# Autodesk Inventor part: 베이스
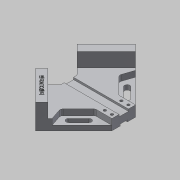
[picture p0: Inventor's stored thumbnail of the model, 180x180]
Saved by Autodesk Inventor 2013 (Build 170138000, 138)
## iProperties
Created: 2019-04
Part Number: 베이스
Material: 알루미늄 6061
Document SubType Name: Modeling
Designer: Administrator
Density: 2.71 g/cm^3
Mass: 603.672 g
Surface Area: 425.327 cm^2
Volume: 222.757 cm^3
Author: Administrator
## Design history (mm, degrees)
sketch "스케치1"
  geometry: L1 (84.853, 0)-(35.355, 49.497); L2 (0, 84.853)-(-35.355, 49.497); L3 (-84.853, 0)-(-20, -64.853); L4 (0, -84.853)-(20, -64.853); L5 (84.853, 0)-(-84.853, 0); L6 (0, 84.853)-(0, -84.853); L7 (-35.355, 49.497)-(-14.005, 28.147); L8 (-14.005, 28.147)-(14.005, 28.147); L9 (14.005, 28.147)-(35.355, 49.497); L10 (-20, -64.853)-(20, -64.853); L11 (20, -64.853)-(84.853, 0); L12 (-20, -64.853)-(0, -84.853); L13 (-35.355, 49.497)-(-84.853, 0); L14 (35.355, 49.497)-(0, 84.853); 4 further points
  constraints: 28 end point, 8 parallel, 5 midpoint, 4 perpendicular, 2 horizontal, 2 vertical alignment, 1 equal length
  dimensions: "d0" = 120 distance of L1.start L2.start; "d2" = 50 distance of L2.start L2.end; "d3" = 40 distance of L3.end L4.end; "d4" = 93 distance between parallel lines of L8 L10; "d6" = 90 deg angle of L7 L13; "d7" = 90 deg angle of L1 L9
extrude "돌출1" new body sketch "스케치1" distance "d8" = 18; taper "d9" = 0 deg
sketch "스케치2"
  geometry: L1 (84.853, 0)-(35.355, 49.497) reference; L2 (35.355, 49.497)-(14.005, 28.147) reference; L3 (-14.005, 28.147)-(-35.355, 49.497) reference; L4 (-35.355, 49.497)-(-84.853, 0) reference; L5 (-84.853, 0)-(-20, -64.853) reference; L6 (20, -64.853)-(84.853, 0) reference; L7 (-74.246, -10.607)-(-24.749, 38.891); L8 (24.749, 38.891)-(74.246, -10.607); 1 further point
  constraints: 4 end point, 4 point on line, 2 perpendicular
  dimensions: "d10" = 15 distance between parallel lines of L7 L4; "d11" = 15 distance between parallel lines of L1 L8
extrude "돌출2" join sketch "스케치2" distance "d12" = 24; taper "d13" = 0 deg
sketch "스케치3"
  geometry: L1 (-74.246, -10.607)-(-20, -64.853) reference; L2 (-70.711, -14.142)-(-49.497, -7.071); L3 (-49.497, -7.071)-(-20, -36.569); L4 (-35.355, 49.497)-(-84.853, 0) reference; L5 (-20, -64.853)-(-20, -36.569); 1 further point
  constraints: 6 end point, 1 parallel, 1 point on line, 1 vertical
  dimensions: "d14" = 20 distance between parallel lines of L3 L1; "d16" = 20 distance from line of L2.start L4; "d17" = 30 distance from line of L2.end L4
extrude "돌출3" cut sketch "스케치3" distance "d18" = 10; taper "d19" = 0 deg
sketch "스케치4"
  geometry: L1 (-20, -64.853)-(-70.711, -14.142) reference; L2 (-52.679, -24.395)-(-35.709, -41.366); L3 (-46.315, -18.031)-(-29.345, -35.002); L4 (-84.853, 0)-(-20, -64.853) reference; L5 (-35.355, 49.497)-(-84.853, 0) reference; A1 r 4.5 centre (-49.497, -21.213) between (-46.315, -18.031) and (-52.679, -24.395); A2 r 4.5 centre (-32.527, -38.184) between (-35.709, -41.366) and (-29.345, -35.002); 1 further point
  constraints: 4 end point, 4 point on circle, 4 tangent, 2 centre point, 1 equal radius
  dimensions: "d20" = 10 distance from line of A1.centre L4; "d21" = 40 distance from line of A1.centre L5; "d22" = 24 distance of A2.centre A1.centre; "d23" = 9 distance between parallel lines of L3 L2; "d24" = 10 distance from line of A2.centre L1
extrude "돌출4" cut sketch "스케치4" stored distance "d25" = 10; taper "d26" = 0 deg
sketch "스케치5"
  geometry: L1 (14.005, 28.147)-(-14.005, 28.147) reference; L2 (-20, -64.853)-(20, -64.853) reference; L3 (-8, 28.147)-(-8, -64.853); L4 (8, 28.147)-(8, -64.853); 1 further point
  constraints: 4 end point, 4 point on line, 2 vertical, 1 parallel
  dimensions: "d27" = 16 distance between parallel lines of L4 L3; "d28" = 8 distance from line of point (0, 0) L3
extrude "돌출5" cut sketch "스케치5" distance "d29" = 3.5; taper "d30" = 0 deg
sketch "스케치6"
  geometry: L1 (20, -64.853)-(-20, -64.853) reference; L2 (-14.005, 28.147)-(14.005, 28.147) reference; L3 (-6, 28.147)-(-6, -64.853); L4 (6, -64.853)-(6, 28.147); 1 further point
  constraints: 4 end point, 4 point on line, 2 vertical, 1 parallel
  dimensions: "d31" = 12 distance between parallel lines of L4 L3; "d32" = 6 distance from line of L4 point (0, 0)
extrude "돌출6" cut sketch "스케치6" distance "d33" = 3; taper "d34" = 0 deg
sketch "스케치7"
  geometry: L1 (20, -64.853)-(70.711, -14.142) reference; L2 (20, -64.853)-(8, -64.853) reference; 5 further points
  constraints: 2 horizontal alignment, 2 vertical alignment
  dimensions: "d35" = 28 distance of point (14, -58.853) point (-14, -58.853); "d37" = 6 distance from line of point (14, -58.853) L2; "d38" = 12 distance of point (14, -46.853) point (14, -58.853); "d39" = 14 horizontal distance of point (0, 0) point (-14, -58.853)
hole "구멍1" sketch "스케치7" at (-14, -58.853), (-14, -46.853), (14, -58.853), (14, -46.853) diameter "d40" = 4.5; stored, may be unused: countersink angle "d44" = 90 deg, drill point angle "d46" = 118 deg; dims "d41" = 6, "d42" = 8, "d43" = 10, "d45" = 8
fillet "모깎기1" dims "d47" = 5
sketch "스케치12"
  geometry: L1 (-35.355, 49.497)-(-84.853, 0) reference; L2 (-24.749, 38.891)-(-35.355, 49.497) reference; 2 further points
  constraints: 1 other
  dimensions: "d50" = 7.5 distance from line of point (-54.801, 19.445) L1; "d51" = 35 distance from line of point (-54.801, 19.445) L2
feature "엠보싱1" sketch "스케치12" dims "d0" = 120, "d2" = 50, "d3" = 40, "d4" = 93, "d6" = 90 deg, "d7" = 15.70796, "d52" = 0.5, "d53" = 0
node "솔리드1"
mirror "대칭1"
